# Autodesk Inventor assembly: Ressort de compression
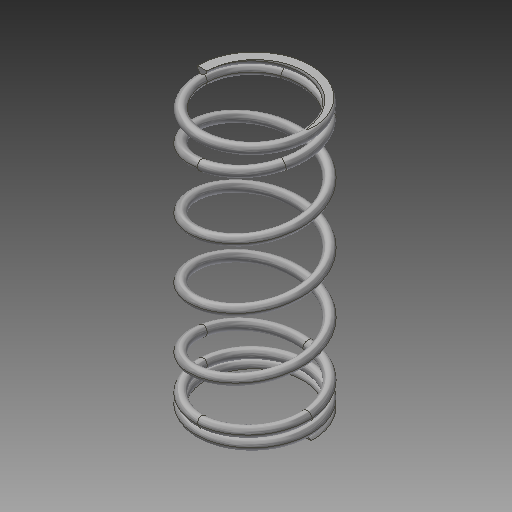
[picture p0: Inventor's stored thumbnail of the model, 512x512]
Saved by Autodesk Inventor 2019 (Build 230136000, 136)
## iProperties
Created: 2018-06
Part Number: Ressort de compression
Document SubType Name: Assembly
Designer: Fabian Perrée
ClientObjectVersion: 1
Author: Fabian Perrée
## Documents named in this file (2)
- C:\Users\Fabian\Google Drive\04_CAO\01_Inventor\Fichiers_exercice_Inventor\Definitif\Capteur\Capteur_V1\Design Accelerator\Ressort de compression2.iam
- C:\Users\Fabian\Google Drive\04_CAO\01_Inventor\Fichiers_exercice_Inventor\Definitif\Capteur\Capteur_V1\Design Accelerator\Ressort de compression12.ipt
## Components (1 placed, 1 different names)
1. Ressort de compression1:1
